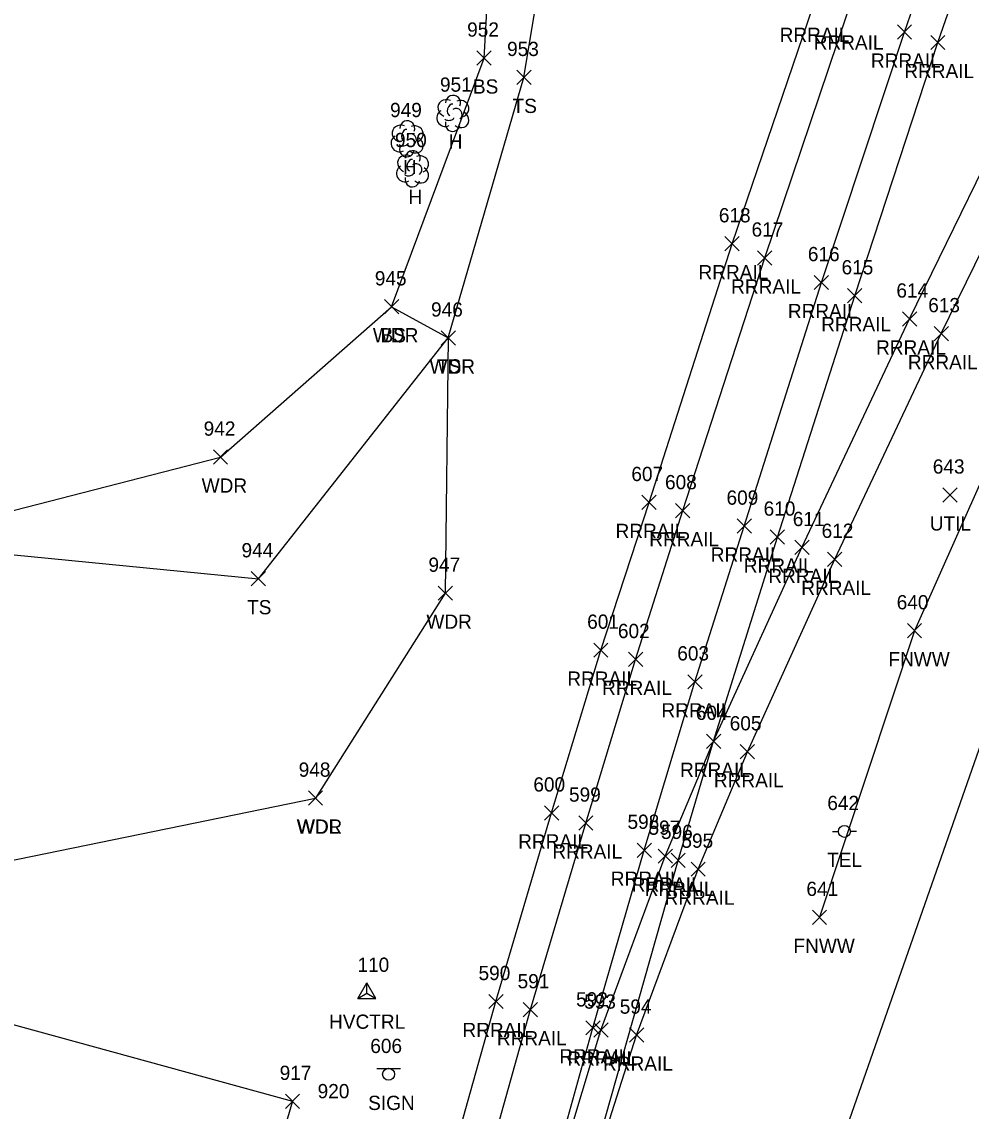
# Model space of a CAD drawing. Extents: x 1767353 to 1772625, y 740790 to 747702.
# Drawn here: x 1770199.3 to 1770332.7, y 742162.8 to 742315.8 of the extents above; entities that cross this region are included whole.
import ezdxf

# ---------------------------------------------------------------- set-up
doc = ezdxf.new("R2010")
doc.units = 0
for name, color, linetype in [('C_A', 7, 'Continuous'), ('C_I', 7, 'Continuous'), ('CPSM', 7, 'Continuous'), ('L_A', 7, 'Continuous'), ('L_I', 7, 'Continuous'), ('L_TIC', 7, 'Continuous'), ('LAWA', 7, 'Continuous'), ('LELB', 7, 'Continuous'), ('LFNC', 7, 'Continuous'), ('LTD', 7, 'Continuous'), ('PET', 7, 'Continuous'), ('R_A', 7, 'Continuous'), ('R_I', 7, 'Continuous'), ('R_TIC', 7, 'Continuous'), ('RDG', 7, 'Continuous'), ('RR', 7, 'Continuous'), ('S_A', 7, 'Continuous'), ('S_I', 7, 'Continuous'), ('SSGN', 7, 'Continuous'), ('U_A', 7, 'Continuous'), ('U_I', 7, 'Continuous'), ('UDEFAULT', 7, 'Continuous'), ('UP', 7, 'Continuous')]:
    doc.layers.add(name, color=color, linetype=linetype)

msp = doc.modelspace()

# ---------------------------------------------------------------- linework, layer by layer
at = {"layer": 'CPSM'}
for p, q in [((1770246.55, 742178.63), (1770247.8, 742180.79)), ((1770246.55, 742178.63), (1770247.8, 742180.79)), ((1770246.55, 742178.63), (1770247.8, 742180.79)), ((1770246.55, 742178.63), (1770247.8, 742180.79)), ((1770246.55, 742178.63), (1770247.8, 742180.79)), ((1770246.55, 742178.63), (1770247.8, 742180.79)), ((1770246.55, 742178.63), (1770247.8, 742180.79)), ((1770249.05, 742178.63), (1770247.8, 742180.79)), ((1770247.8, 742179.35), (1770247.8, 742180.79)), ((1770249.05, 742178.63), (1770247.8, 742180.79)), ((1770247.8, 742179.35), (1770247.8, 742180.79)), ((1770249.05, 742178.63), (1770247.8, 742180.79)), ((1770247.8, 742179.35), (1770247.8, 742180.79)), ((1770249.05, 742178.63), (1770247.8, 742180.79)), ((1770247.8, 742179.35), (1770247.8, 742180.79)), ((1770249.05, 742178.63), (1770247.8, 742180.79)), ((1770247.8, 742179.35), (1770247.8, 742180.79)), ((1770249.05, 742178.63), (1770247.8, 742180.79)), ((1770247.8, 742179.35), (1770247.8, 742180.79)), ((1770249.05, 742178.63), (1770247.8, 742180.79)), ((1770247.8, 742179.35), (1770247.8, 742180.79)), ((1770246.55, 742178.63), (1770247.8, 742179.35)), ((1770246.55, 742178.63), (1770247.8, 742179.35)), ((1770246.55, 742178.63), (1770247.8, 742179.35)), ((1770246.55, 742178.63), (1770247.8, 742179.35)), ((1770246.55, 742178.63), (1770247.8, 742179.35)), ((1770246.55, 742178.63), (1770247.8, 742179.35)), ((1770246.55, 742178.63), (1770247.8, 742179.35)), ((1770246.55, 742178.63), (1770249.05, 742178.63)), ((1770246.55, 742178.63), (1770249.05, 742178.63)), ((1770246.55, 742178.63), (1770249.05, 742178.63)), ((1770246.55, 742178.63), (1770249.05, 742178.63)), ((1770246.55, 742178.63), (1770249.05, 742178.63)), ((1770246.55, 742178.63), (1770249.05, 742178.63)), ((1770246.55, 742178.63), (1770249.05, 742178.63)), ((1770247.8, 742179.35), (1770247.8, 742179.35)), ((1770247.8, 742179.35), (1770249.05, 742178.63)), ((1770247.8, 742179.35), (1770247.8, 742179.35)), ((1770247.8, 742179.35), (1770249.05, 742178.63)), ((1770247.8, 742179.35), (1770247.8, 742179.35)), ((1770247.8, 742179.35), (1770249.05, 742178.63)), ((1770247.8, 742179.35), (1770247.8, 742179.35)), ((1770247.8, 742179.35), (1770249.05, 742178.63)), ((1770247.8, 742179.35), (1770247.8, 742179.35)), ((1770247.8, 742179.35), (1770249.05, 742178.63)), ((1770247.8, 742179.35), (1770247.8, 742179.35)), ((1770247.8, 742179.35), (1770249.05, 742178.63)), ((1770247.8, 742179.35), (1770247.8, 742179.35)), ((1770247.8, 742179.35), (1770249.05, 742178.63))]:
    msp.add_line(p, q, dxfattribs=at)
at = {"layer": 'L_TIC'}
for points in [[(1770263.27, 742309.68), (1770265.27, 742311.68)], [(1770265.27, 742309.68), (1770263.27, 742311.68)], [(1770268.87, 742306.96), (1770270.87, 742308.96)], [(1770270.87, 742306.96), (1770268.87, 742308.96)], [(1770250.29, 742274.75), (1770252.29, 742276.75)], [(1770252.29, 742274.75), (1770250.29, 742276.75)], [(1770250.29, 742274.75), (1770252.29, 742276.75)], [(1770252.29, 742274.75), (1770250.29, 742276.75)], [(1770258.25, 742270.37), (1770260.25, 742272.37)], [(1770260.25, 742270.37), (1770258.25, 742272.37)], [(1770258.25, 742270.37), (1770260.25, 742272.37)], [(1770260.25, 742270.37), (1770258.25, 742272.37)], [(1770226.24, 742253.64), (1770228.24, 742255.64)], [(1770228.24, 742253.64), (1770226.24, 742255.64)], [(1770231.57, 742236.56), (1770233.57, 742238.56)], [(1770233.57, 742236.56), (1770231.57, 742238.56)], [(1770257.82, 742234.53), (1770259.82, 742236.53)], [(1770259.82, 742234.53), (1770257.82, 742236.53)], [(1770323.75, 742229.26), (1770325.75, 742231.26)], [(1770325.75, 742229.26), (1770323.75, 742231.26)], [(1770239.59, 742205.75), (1770241.59, 742207.75)], [(1770241.59, 742205.75), (1770239.59, 742207.75)], [(1770239.59, 742205.75), (1770241.59, 742207.75)], [(1770241.59, 742205.75), (1770239.59, 742207.75)], [(1770310.41, 742189.01), (1770312.41, 742191.01)], [(1770312.41, 742189.01), (1770310.41, 742191.01)]]:
    msp.add_lwpolyline(points, dxfattribs=at)
at = {"layer": 'LAWA'}
for points in [[(1770130.05, 742182.04), (1770146.86, 742211.98), (1770165.11, 742221.35), (1770177.74, 742232), (1770191.89, 742245.53), (1770227.24, 742254.64), (1770251.29, 742275.75), (1770259.25, 742271.37), (1770258.82, 742235.53), (1770240.59, 742206.75)], [(1770130.05, 742182.04), (1770143.88, 742179.38), (1770162.33, 742204.96), (1770193.25, 742197.07), (1770240.59, 742206.75)]]:
    msp.add_lwpolyline(points, dxfattribs=at)
at = {"layer": 'LELB'}
for points in [[(1770162.33, 742204.96), (1770182.69, 742228.32), (1770195.35, 742241.18), (1770232.57, 742237.56), (1770259.25, 742271.37), (1770269.87, 742307.96), (1770289.26, 742424.34), (1770288.5, 742547.79), (1770295.74, 742644.73), (1770282.22, 742645.21)], [(1770251.29, 742275.75), (1770264.27, 742310.68), (1770270.74, 742425.56), (1770277.6, 742545.58), (1770282.22, 742645.21)]]:
    msp.add_lwpolyline(points, dxfattribs=at)
at = {"layer": 'LFNC'}
msp.add_lwpolyline([(1770365.47, 742313.6), (1770350.97, 742285.69), (1770337.29, 742258.44), (1770324.75, 742230.26), (1770311.41, 742190.01)], dxfattribs=at)
at = {"layer": 'LTD'}
for p, q in [((1770259.87, 742302.95), (1770259.87, 742302.95)), ((1770259.87, 742302.95), (1770259.87, 742302.95)), ((1770253.44, 742299.38), (1770253.44, 742299.38)), ((1770253.44, 742299.38), (1770253.44, 742299.38)), ((1770254.21, 742295.17), (1770254.21, 742295.17)), ((1770254.21, 742295.17), (1770254.21, 742295.17))]:
    msp.add_line(p, q, dxfattribs=at)
for centre in [(1770259.92, 742304.39), (1770253.49, 742300.82), (1770254.26, 742296.61)]:
    msp.add_arc(centre, 1.05, 335.5272, 180.9563, dxfattribs=at)
for centre, major_axis, ratio, start_param, end_param in [((1770259.08, 742303.62), (1.21, -0.51), 0.895232, 1.570796, 4.712389), ((1770259.66, 742303.41), (-0.208, -0.792), 0.645439, 3.141593, 6.283185), ((1770260.37, 742302.79), (-0.5, 0.667), 0.989748, 3.141593, 6.283185), ((1770260.91, 742303.54), (-1.14, -0.48), 0.949671, 1.570796, 4.712389), ((1770258.79, 742302.24), (0.58, -1.04), 0.959034, 3.141593, 6.283185), ((1770259.41, 742302.2), (-0.625, -0.083), 0.423636, 0, 3.141593), ((1770260.87, 742302.12), (-1.09, 0.79), 0.841452, 1.570796, 4.712389), ((1770252.65, 742300.05), (1.21, -0.51), 0.895232, 1.570796, 4.712389), ((1770253.24, 742299.84), (-0.208, -0.792), 0.645439, 3.141593, 6.283185), ((1770254.49, 742299.97), (-1.14, -0.48), 0.949671, 1.570796, 4.712389), ((1770259.87, 742301.45), (0.26, 1.06), 0.942809, 1.570796, 4.712389), ((1770252.36, 742298.67), (0.58, -1.04), 0.959034, 3.141593, 6.283185), ((1770253.94, 742299.22), (-0.5, 0.667), 0.989748, 3.141593, 6.283185), ((1770254.44, 742298.55), (-1.09, 0.79), 0.841452, 1.570796, 4.712389), ((1770253.44, 742297.88), (0.26, 1.06), 0.942809, 1.570796, 4.712389), ((1770252.99, 742298.63), (-0.625, -0.083), 0.423636, 0, 3.141593), ((1770253.42, 742295.84), (1.21, -0.51), 0.895232, 1.570796, 4.712389), ((1770254, 742295.63), (-0.208, -0.792), 0.645439, 3.141593, 6.283185), ((1770255.25, 742295.76), (-1.14, -0.48), 0.949671, 1.570796, 4.712389), ((1770253.13, 742294.46), (0.58, -1.04), 0.959034, 3.141593, 6.283185), ((1770253.75, 742294.42), (-0.625, -0.083), 0.423636, 0, 3.141593), ((1770254.71, 742295.01), (-0.5, 0.667), 0.989748, 3.141593, 6.283185), ((1770255.21, 742294.34), (-1.09, 0.79), 0.841452, 1.570796, 4.712389), ((1770254.21, 742293.67), (0.26, 1.06), 0.942809, 1.570796, 4.712389)]:
    msp.add_ellipse(centre, major_axis=major_axis, ratio=ratio, start_param=start_param, end_param=end_param, dxfattribs=at)
at = {"layer": 'PET'}
msp.add_lwpolyline([(1770243.74, 741939.41), (1770255.24, 741954.28), (1770270.92, 742018.28), (1770293.62, 742096.86), (1770309.99, 742145.51), (1770335.13, 742217.35), (1770370.55, 742306.75), (1770390.86, 742357.46), (1770403.22, 742384.01), (1770418.01, 742412.4), (1770432.62, 742430.87), (1770448.87, 742440.9), (1770468.46, 742446.31), (1770490.36, 742448.75), (1770521.27, 742448.09), (1770553.51, 742444.86)], dxfattribs=at)
at = {"layer": 'R_TIC'}
for points in [[(1770322.34, 742313.32), (1770324.34, 742315.32)], [(1770324.34, 742313.32), (1770322.34, 742315.32)], [(1770327.03, 742311.86), (1770329.03, 742313.86)], [(1770329.03, 742311.86), (1770327.03, 742313.86)], [(1770298.11, 742283.6), (1770300.11, 742285.6)], [(1770300.11, 742283.6), (1770298.11, 742285.6)], [(1770302.7, 742281.6), (1770304.7, 742283.6)], [(1770304.7, 742281.6), (1770302.7, 742283.6)], [(1770310.67, 742278.15), (1770312.67, 742280.15)], [(1770312.67, 742278.15), (1770310.67, 742280.15)], [(1770315.35, 742276.3), (1770317.35, 742278.3)], [(1770317.35, 742276.3), (1770315.35, 742278.3)], [(1770323.06, 742273.04), (1770325.06, 742275.04)], [(1770325.06, 742273.04), (1770323.06, 742275.04)], [(1770327.52, 742270.98), (1770329.52, 742272.98)], [(1770329.52, 742270.98), (1770327.52, 742272.98)], [(1770286.46, 742247.27), (1770288.46, 742249.27)], [(1770288.46, 742247.27), (1770286.46, 742249.27)], [(1770291.18, 742246.12), (1770293.18, 742248.12)], [(1770293.18, 742246.12), (1770291.18, 742248.12)], [(1770299.84, 742243.95), (1770301.84, 742245.95)], [(1770301.84, 742243.95), (1770299.84, 742245.95)], [(1770304.48, 742242.41), (1770306.48, 742244.41)], [(1770306.48, 742242.41), (1770304.48, 742244.41)], [(1770307.93, 742240.95), (1770309.93, 742242.95)], [(1770309.93, 742240.95), (1770307.93, 742242.95)], [(1770312.54, 742239.29), (1770314.54, 742241.29)], [(1770314.54, 742239.29), (1770312.54, 742241.29)], [(1770279.68, 742226.53), (1770281.68, 742228.53)], [(1770281.68, 742226.53), (1770279.68, 742228.53)], [(1770284.57, 742225.22), (1770286.57, 742227.22)], [(1770286.57, 742225.22), (1770284.57, 742227.22)], [(1770292.9, 742222.08), (1770294.9, 742224.08)], [(1770294.9, 742222.08), (1770292.9, 742224.08)], [(1770295.52, 742213.73), (1770297.52, 742215.73)], [(1770297.52, 742213.73), (1770295.52, 742215.73)], [(1770295.52, 742213.73), (1770297.52, 742215.73)], [(1770297.52, 742213.73), (1770295.52, 742215.73)], [(1770300.28, 742212.26), (1770302.28, 742214.26)], [(1770302.28, 742212.26), (1770300.28, 742214.26)], [(1770272.77, 742203.67), (1770274.77, 742205.67)], [(1770274.77, 742203.67), (1770272.77, 742205.67)], [(1770277.58, 742202.25), (1770279.58, 742204.25)], [(1770279.58, 742202.25), (1770277.58, 742204.25)], [(1770285.79, 742198.43), (1770287.79, 742200.43)], [(1770287.79, 742198.43), (1770285.79, 742200.43)], [(1770288.74, 742197.6), (1770290.74, 742199.6)], [(1770290.74, 742197.6), (1770288.74, 742199.6)], [(1770290.55, 742197.01), (1770292.55, 742199.01)], [(1770292.55, 742197.01), (1770290.55, 742199.01)], [(1770293.36, 742195.77), (1770295.36, 742197.77)], [(1770295.36, 742195.77), (1770293.36, 742197.77)], [(1770264.95, 742177.19), (1770266.95, 742179.19)], [(1770266.95, 742177.19), (1770264.95, 742179.19)], [(1770269.79, 742176.04), (1770271.79, 742178.04)], [(1770271.79, 742176.04), (1770269.79, 742178.04)], [(1770278.57, 742173.49), (1770280.57, 742175.49)], [(1770280.57, 742173.49), (1770278.57, 742175.49)], [(1770279.69, 742173.18), (1770281.69, 742175.18)], [(1770281.69, 742173.18), (1770279.69, 742175.18)], [(1770284.7, 742172.47), (1770286.7, 742174.47)], [(1770286.7, 742172.47), (1770284.7, 742174.47)], [(1770236.36, 742163.17), (1770238.36, 742165.17)], [(1770238.36, 742163.17), (1770236.36, 742165.17)]]:
    msp.add_lwpolyline(points, dxfattribs=at)
at = {"layer": 'RDG'}
msp.add_lwpolyline([(1770154.78, 742038.81), (1770156.34, 742046.84), (1770145.55, 742054.8), (1770165.8, 742147.32), (1770178.77, 742180.23), (1770237.36, 742164.17), (1770220.59, 742107.22)], dxfattribs=at)
at = {"layer": 'RR'}
for points in [[(1770221.78, 741982.04), (1770226.9, 742005.14), (1770231.58, 742026.58), (1770238.97, 742057.62), (1770247.46, 742091.31), (1770255.17, 742120.86), (1770262.38, 742147.12), (1770270.79, 742177.04), (1770278.58, 742203.25), (1770285.57, 742226.22), (1770292.18, 742247.12), (1770303.7, 742282.6), (1770315.3, 742316.87), (1770330.35, 742359.31), (1770344.25, 742396.26), (1770362.68, 742444.08), (1770381.25, 742488.48), (1770399.89, 742531.75), (1770427.72, 742593.02), (1770459.92, 742661.06), (1770775.2, 743314.07), (1770996.39, 743772.66), (1771192.02, 744177.67), (1771329.71, 744462.72)], [(1770217.88, 741982.89), (1770224.63, 742006.05), (1770231.58, 742026.58), (1770242.49, 742057.3), (1770253.86, 742089.03), (1770263.22, 742117.76), (1770271, 742143.83), (1770279.57, 742174.49), (1770286.79, 742199.43), (1770293.9, 742223.08), (1770300.84, 742244.95), (1770311.67, 742279.15), (1770323.34, 742314.32), (1770337.98, 742356.11), (1770351.9, 742393.8), (1770370.52, 742441.44), (1770388.76, 742485.07), (1770407.79, 742528.71), (1770435.51, 742589.24), (1770468.44, 742657.89), (1770783.17, 743309.95), (1771004.51, 743768.91), (1771200.35, 744174.24), (1771337.45, 744458.43)], [(1770217.02, 741983.21), (1770222.11, 742006.18), (1770226.99, 742028.12), (1770234.33, 742059.23), (1770242.65, 742092.71), (1770250.33, 742121.94), (1770257.59, 742148.49), (1770265.95, 742178.19), (1770273.77, 742204.67), (1770280.68, 742227.53), (1770287.46, 742248.27), (1770299.11, 742284.6), (1770310.51, 742317.94), (1770325.96, 742361.53), (1770339.5, 742397.74), (1770358.03, 742445.88), (1770376.8, 742490.97), (1770395.2, 742533.35), (1770423.54, 742595.68), (1770455.2, 742662.62), (1770770.92, 743316.68), (1770991.9, 743774.87)], [(1770222.72, 741981.76), (1770229.32, 742004.36), (1770235.77, 742023.83), (1770247.09, 742055.41), (1770258.52, 742087.39), (1770268.11, 742116.55), (1770275.73, 742142.21), (1770291.55, 742198.01), (1770296.52, 742214.73), (1770305.48, 742243.41), (1770316.35, 742277.3), (1770328.03, 742312.86), (1770342.4, 742354.07), (1770356.59, 742392.13), (1770375.3, 742439.98), (1770392.87, 742482.18), (1770412.29, 742526.82), (1770439.88, 742586.94), (1770472.88, 742655.84), (1770787.34, 743307.49), (1771008.99, 743766.96)], [(1770271.52, 742143.69), (1770280.69, 742174.18), (1770289.74, 742198.6), (1770296.52, 742214.73), (1770308.93, 742241.95), (1770324.06, 742274.04), (1770340.68, 742308.04), (1770360.15, 742345.64), (1770381.03, 742382.61), (1770407.02, 742424.16), (1770425.18, 742450.58), (1770450.26, 742483.52), (1770473.18, 742510.79), (1770518.15, 742562.81), (1770572.7, 742627.85), (1770598.36, 742661.22), (1770630.52, 742706.14), (1770655.11, 742743.9), (1770674.5, 742775.55), (1770683.79, 742791.45), (1770706.15, 742833.16), (1770731.07, 742883.64), (1770775.22, 742979.87)], [(1770275.73, 742142.21), (1770285.7, 742173.47), (1770294.36, 742196.77), (1770301.28, 742213.26), (1770313.54, 742240.29), (1770328.52, 742271.98), (1770345.02, 742305.68), (1770363.97, 742342.43), (1770385.56, 742380.58), (1770410.92, 742420.89), (1770428.56, 742446.86), (1770454.89, 742481.33), (1770476.7, 742507.31), (1770522.14, 742559.86), (1770576.25, 742624.32), (1770602.26, 742658.04), (1770634.11, 742702.9), (1770659.93, 742742.21), (1770678.83, 742773.23), (1770687.73, 742788.35), (1770710.35, 742830.29), (1770735.06, 742880.72), (1770779.65, 742978.02)]]:
    msp.add_lwpolyline(points, dxfattribs=at)
at = {"layer": 'SSGN'}
for p, q in [((1770249.21, 742168.8), (1770252.54, 742168.8)), ((1770250.86, 742167.97), (1770250.86, 742167.97))]:
    msp.add_line(p, q, dxfattribs=at)
msp.add_circle((1770250.86, 742167.97), 0.833, dxfattribs=at)
at = {"layer": 'UDEFAULT'}
for points in [[(1770328.73, 742248.32), (1770330.73, 742250.32)], [(1770330.73, 742248.32), (1770328.73, 742250.32)]]:
    msp.add_lwpolyline(points, dxfattribs=at)
at = {"layer": 'UP'}
for p, q in [((1770313.25, 742202.07), (1770314.08, 742202.07)), ((1770314.91, 742202.07), (1770314.91, 742202.07)), ((1770316.58, 742202.07), (1770315.74, 742202.07)), ((1770315.74, 742202.07), (1770315.74, 742202.07)), ((1770316.58, 742202.07), (1770316.58, 742202.07))]:
    msp.add_line(p, q, dxfattribs=at)
msp.add_circle((1770314.91, 742202.07), 0.833, dxfattribs=at)

# ---------------------------------------------------------------- texts
at = {"layer": 'C_A'}
msp.add_text('HVCTRL', height=2, dxfattribs=at).set_placement((1770242.5, 742174.35))
msp.add_text('HVCTRL', height=2, dxfattribs=at).set_placement((1770242.5, 742174.35))
msp.add_text('HVCTRL', height=2, dxfattribs=at).set_placement((1770242.5, 742174.35))
msp.add_text('HVCTRL', height=2, dxfattribs=at).set_placement((1770242.5, 742174.35))
msp.add_text('HVCTRL', height=2, dxfattribs=at).set_placement((1770242.5, 742174.35))
msp.add_text('HVCTRL', height=2, dxfattribs=at).set_placement((1770242.5, 742174.35))
msp.add_text('HVCTRL', height=2, dxfattribs=at).set_placement((1770242.5, 742174.35))
at = {"layer": 'C_I'}
msp.add_text('110', height=2, dxfattribs=at).set_placement((1770246.49, 742182.35))
msp.add_text('110', height=2, dxfattribs=at).set_placement((1770246.49, 742182.35))
msp.add_text('110', height=2, dxfattribs=at).set_placement((1770246.49, 742182.35))
msp.add_text('110', height=2, dxfattribs=at).set_placement((1770246.49, 742182.35))
msp.add_text('110', height=2, dxfattribs=at).set_placement((1770246.49, 742182.35))
msp.add_text('110', height=2, dxfattribs=at).set_placement((1770246.49, 742182.35))
msp.add_text('110', height=2, dxfattribs=at).set_placement((1770246.49, 742182.35))
at = {"layer": 'L_A'}
for s, p in [('BS', (1770262.71, 742305.68)), ('TS', (1770268.28, 742302.96)), ('H', (1770259.31, 742297.95)), ('H', (1770252.88, 742294.38)), ('H', (1770253.65, 742290.17)), ('WDR', (1770248.66, 742270.75)), ('BS', (1770249.73, 742270.75)), ('WDR', (1770256.61, 742266.37)), ('TS', (1770257.66, 742266.37)), ('WDR', (1770224.6, 742249.64)), ('TS', (1770230.98, 742232.56)), ('WDR', (1770256.18, 742230.53)), ('FNWW', (1770321.09, 742225.26)), ('WDR', (1770237.95, 742201.75)), ('WDL', (1770238.01, 742201.75)), ('FNWW', (1770307.75, 742185.01))]:
    msp.add_text(s, height=2, dxfattribs=at).set_placement(p)
at = {"layer": 'L_I'}
for s, p in [('952', (1770261.9, 742313.68)), ('953', (1770267.51, 742310.96)), ('951', (1770258.08, 742305.95)), ('949', (1770251.07, 742302.38)), ('950', (1770251.76, 742298.17)), ('945', (1770248.93, 742278.75)), ('945', (1770248.93, 742278.75)), ('946', (1770256.83, 742274.37)), ('946', (1770256.83, 742274.37)), ('942', (1770224.88, 742257.64)), ('944', (1770230.2, 742240.56)), ('947', (1770256.46, 742238.53)), ('640', (1770322.25, 742233.26)), ('948', (1770238.23, 742209.75)), ('948', (1770238.23, 742209.75)), ('641', (1770309.56, 742193.01)), ('920', (1770240.89, 742164.6))]:
    msp.add_text(s, height=2, dxfattribs=at).set_placement(p)
at = {"layer": 'R_A'}
for p in [(1770305.8, 742312.94), (1770310.59, 742311.87), (1770318.63, 742309.32), (1770323.32, 742307.86), (1770294.4, 742279.6), (1770298.99, 742277.6), (1770306.96, 742274.15), (1770311.64, 742272.3), (1770319.35, 742269.04), (1770323.82, 742266.98), (1770282.75, 742243.27), (1770287.48, 742242.12), (1770296.13, 742239.95), (1770300.77, 742238.41), (1770304.22, 742236.95), (1770308.84, 742235.29), (1770275.97, 742222.53), (1770280.86, 742221.22), (1770289.2, 742218.08), (1770291.81, 742209.73), (1770291.81, 742209.73), (1770296.57, 742208.26), (1770269.07, 742199.67), (1770273.87, 742198.25), (1770282.08, 742194.43), (1770285.03, 742193.6), (1770286.84, 742193.01), (1770289.65, 742191.77), (1770261.24, 742173.19), (1770266.08, 742172.04), (1770274.86, 742169.49), (1770275.98, 742169.18), (1770280.99, 742168.47)]:
    msp.add_text('RRRAIL', height=2, dxfattribs=at).set_placement(p)
at = {"layer": 'R_I'}
for s, p in [('618', (1770297.26, 742287.6)), ('617', (1770301.86, 742285.6)), ('616', (1770309.77, 742282.15)), ('615', (1770314.5, 742280.3)), ('614', (1770322.21, 742277.04)), ('613', (1770326.68, 742274.98)), ('607', (1770284.97, 742251.27)), ('608', (1770289.7, 742250.12)), ('609', (1770298.34, 742247.95)), ('610', (1770303.55, 742246.41)), ('611', (1770307.65, 742244.95)), ('612', (1770311.7, 742243.29)), ('601', (1770278.76, 742230.53)), ('602', (1770283.08, 742229.22)), ('603', (1770291.42, 742226.08)), ('604', (1770294.03, 742217.73)), ('604', (1770294.03, 742217.73)), ('605', (1770298.79, 742216.26)), ('600', (1770271.2, 742207.67)), ('599', (1770276.21, 742206.25)), ('598', (1770284.43, 742202.43)), ('597', (1770287.38, 742201.6)), ('596', (1770289.13, 742201.01)), ('595', (1770292, 742199.77)), ('590', (1770263.5, 742181.19)), ('591', (1770268.99, 742180.04)), ('592', (1770277.2, 742177.49)), ('593', (1770278.33, 742177.18)), ('594', (1770283.34, 742176.47)), ('917', (1770235.56, 742167.17))]:
    msp.add_text(s, height=2, dxfattribs=at).set_placement(p)
at = {"layer": 'S_A'}
msp.add_text('SIGN', height=2, dxfattribs=at).set_placement((1770247.99, 742162.95))
at = {"layer": 'S_I'}
msp.add_text('606', height=2, dxfattribs=at).set_placement((1770248.29, 742170.95))
at = {"layer": 'U_A'}
for s, p in [('UTIL', (1770326.9, 742244.32)), ('TEL', (1770312.47, 742197.07))]:
    msp.add_text(s, height=2, dxfattribs=at).set_placement(p)
at = {"layer": 'U_I'}
for s, p in [('643', (1770327.32, 742252.32)), ('642', (1770312.5, 742205.07))]:
    msp.add_text(s, height=2, dxfattribs=at).set_placement(p)

doc.saveas('drawing.dxf')
